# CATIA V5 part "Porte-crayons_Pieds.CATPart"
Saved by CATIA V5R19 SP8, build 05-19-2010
Part number: Pieds_Pot_Crayons
Publications: "Face gauche", "Face droite", "Face haut", "Face bas"
Bounding box of the stored display mesh (mm): x -33.375 to 3, y 0 to 3, z 2.857 to 70
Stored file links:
  D:\Documents\1_Travail\1 - ac-limoges.fr\OneDrive - ac-limoges.fr\STI2D_Turgot\3 - Supports\Pot_à_Crayons\Maquette numérique\Maquette_eleve\Porte-crayons_Pieds.CATPart
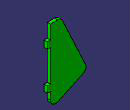
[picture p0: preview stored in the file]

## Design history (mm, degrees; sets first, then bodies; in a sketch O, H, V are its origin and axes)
SheetMetalParameters1: Thickness 3, BendRadius 4, KFactor 0.356492 {= log(min(100,max(20*SheetMetalParameters1.BendRadius,SheetMetalParameters1.Thickness)/SheetMetalParameters1.Thickness))/log(100)/2}, ReliefRadialLength 1, ReliefAxialLength 2, MinimumBendRadius 0
Body1 "Pied" (main body)
  Sketch1 on zx-plane, origin (0, 0, 0), H (-1, 0, 0), V (0, 0, 1)
    point P1 (0, 0)
    line L1 (0, 0) -> (0, 15)
    point P2 (0, 70)
    line L2 (0, 70) -> (10, 70)
    line L3 (10, 70) -> (35.0255, 16.3327)
    line L4 (35.0255, 16.3327) -> (0, 0)
    point P5 (0, 21)
    line L5 (0, 21) -> (-3, 21)
    line L6 (-3, 21) -> (-3, 15)
    line L7 (-3, 15) -> (0, 15)
    point P9 (0, 57)
    line L8 (0, 57) -> (-3, 57)
    line L9 (-3, 57) -> (-3, 51)
    line L10 (-3, 51) -> (0, 51)
    line L11 (0, 57) -> (0, 70)
    line L12 (0, 21) -> (0, 51)
    point P13 (0, 9.2413)
    angle L3 L4 = 90
    distance L8 L10 = 6 {= SheetMetalParameters1.Thickness *2}
    distance L5 L7 = 6 {= SheetMetalParameters1.Thickness *2}
    distance P1 P2 = 70
    length L2 = 10
    angle L4 H = 25
    distance L12 L6 = 3 {= SheetMetalParameters1.Thickness}
    distance L7 O = 15
    distance L5 L10 = 30
    vertical: L1 V, L6 V, L9 V, L11 V, L12 V
    horizontal: L2 H, L5 H, L7 H, L8 H, L10 H
    coincidence: P5 L1, P9 L1, L1 L11, L1 L12, L1 V, P1 H, L6 L9
  Wall1: Thickness 3, Profile Sketch1
  Corner1: CornerRadius 5, CornerChamferEdges (edge [face of Wall1 | face of Wall1]; edge [face of Wall1 | face of Wall1]; edge [face of Wall1 | face of Wall1])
